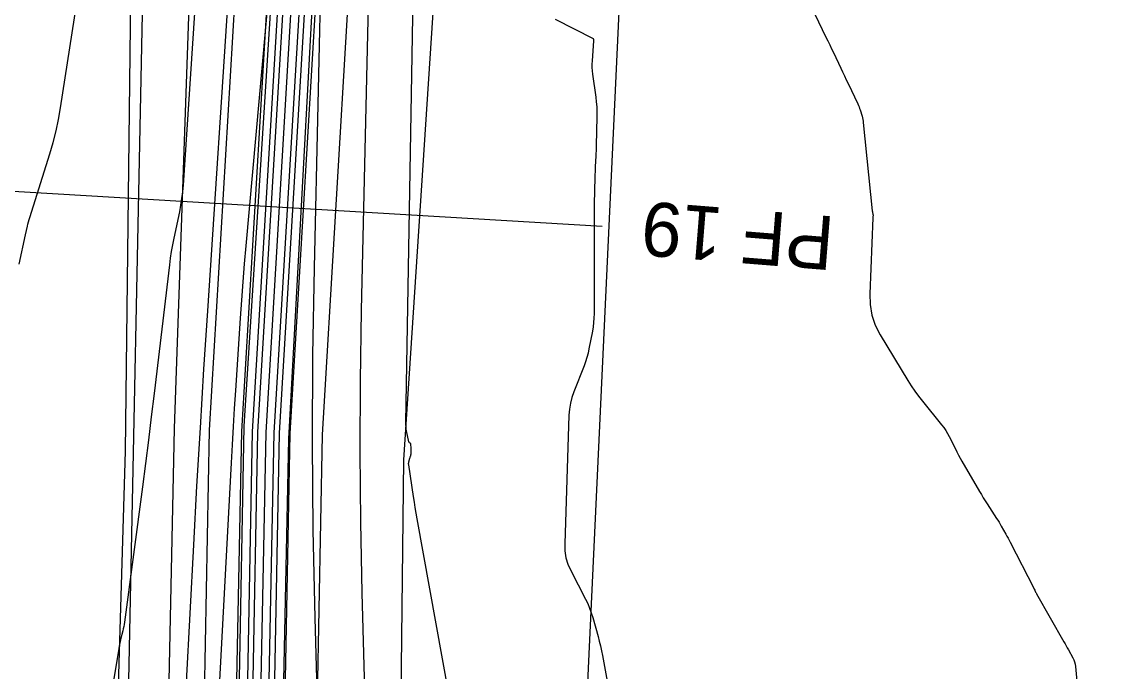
# Model space of a CAD drawing. Extents: x -534410 to -534262, y -1190162 to -1189584.
# Drawn here: x -534369.58 to -534349.13, y -1189689.33 to -1189677.27 of the extents above; entities that cross this region are included whole.
import ezdxf

# ---------------------------------------------------------------- set-up
doc = ezdxf.new("R2010")
doc.units = 0
for name, color, linetype in [('30', 7, 'Continuous'), ('31', 7, 'Continuous'), ('_linie', 7, 'Continuous'), ('_N_osa', 7, 'Continuous'), ('_N_tenká', 7, 'Continuous'), ('_N_tenká_velmi', 7, 'Continuous'), ('_N_text', 7, 'Continuous'), ('_tenka', 7, 'Continuous'), ('Default', 7, 'Continuous'), ('Hranice parcel', 7, 'Continuous')]:
    doc.layers.add(name, color=color, linetype=linetype)

msp = doc.modelspace()

# ---------------------------------------------------------------- linework, layer by layer
at = {"layer": '30'}
for points in [[(-534359.666, -1189700.773), (-534362.25, -1189686.484), (-534362.268, -1189686.382), (-534362.286, -1189686.279), (-534362.302, -1189686.177), (-534362.318, -1189686.074), (-534362.407, -1189685.485), (-534362.409, -1189685.471), (-534362.409, -1189685.457), (-534362.407, -1189685.444), (-534362.404, -1189685.43), (-534362.384, -1189685.358), (-534362.381, -1189685.35), (-534362.378, -1189685.341), (-534362.371, -1189685.323), (-534362.369, -1189685.317), (-534362.368, -1189685.311), (-534362.365, -1189685.295), (-534362.364, -1189685.289), (-534362.364, -1189685.286), (-534362.364, -1189685.219), (-534362.364, -1189685.208), (-534362.363, -1189685.181), (-534362.363, -1189685.17), (-534362.363, -1189685.166), (-534362.366, -1189685.115), (-534362.366, -1189685.108), (-534362.365, -1189685.095), (-534362.365, -1189685.092), (-534362.366, -1189685.09), (-534362.367, -1189685.089), (-534362.369, -1189685.087), (-534362.392, -1189685.076), (-534362.396, -1189685.073), (-534362.399, -1189685.07), (-534362.401, -1189685.066), (-534362.403, -1189685.061), (-534362.445, -1189684.854), (-534362.451, -1189684.817), (-534362.456, -1189684.781), (-534362.458, -1189684.744), (-534362.459, -1189684.707), (-534362.015, -1189658.872)], [(-534365.801, -1189668.276), (-534366.596, -1189680.297), (-534366.607, -1189680.421), (-534366.622, -1189680.545), (-534366.641, -1189680.668), (-534366.664, -1189680.791), (-534366.767, -1189681.279), (-534366.792, -1189681.402), (-534366.813, -1189681.525), (-534366.832, -1189681.648), (-534366.848, -1189681.772), (-534367.133, -1189684.164), (-534367.186, -1189684.597), (-534367.239, -1189685.03), (-534367.295, -1189685.462), (-534367.351, -1189685.894), (-534367.683, -1189688.404), (-534367.689, -1189688.445), (-534367.697, -1189688.486), (-534367.705, -1189688.527), (-534367.715, -1189688.567), (-534367.756, -1189688.728), (-534367.765, -1189688.768), (-534367.774, -1189688.809), (-534367.783, -1189688.85), (-534367.79, -1189688.891), (-534368.719, -1189694.516)], [(-534363.782, -1189701.447), (-534364.144, -1189688.321), (-534364.178, -1189686.697), (-534364.192, -1189685.074), (-534364.185, -1189683.451), (-534364.158, -1189681.827), (-534363.949, -1189672.734)], [(-534364.818, -1189674.62), (-534365.429, -1189681.422), (-534365.458, -1189681.757), (-534365.485, -1189682.092), (-534365.51, -1189682.427), (-534365.533, -1189682.763), (-534365.622, -1189684.105), (-534365.644, -1189684.441), (-534365.664, -1189684.776), (-534365.684, -1189685.112), (-534365.702, -1189685.448), (-534366.553, -1189701.366)], [(-534354.935, -1189676.979), (-534354.661, -1189677.55), (-534354.626, -1189677.622), (-534354.592, -1189677.693), (-534354.558, -1189677.765), (-534354.524, -1189677.837), (-534354.387, -1189678.125), (-534354.353, -1189678.197), (-534354.319, -1189678.269), (-534354.284, -1189678.341), (-534354.25, -1189678.413), (-534354.07, -1189678.79), (-534354.058, -1189678.817), (-534354.046, -1189678.845), (-534354.036, -1189678.874), (-534354.027, -1189678.902), (-534353.992, -1189679.018), (-534353.984, -1189679.047), (-534353.978, -1189679.077), (-534353.973, -1189679.107), (-534353.969, -1189679.136), (-534353.802, -1189680.773), (-534353.801, -1189680.78), (-534353.8, -1189680.787), (-534353.799, -1189680.794), (-534353.797, -1189680.802), (-534353.79, -1189680.833), (-534353.789, -1189680.839), (-534353.788, -1189680.845), (-534353.788, -1189680.85), (-534353.788, -1189680.856), (-534353.789, -1189680.884), (-534353.789, -1189680.901), (-534353.849, -1189682.312), (-534353.844, -1189682.513), (-534353.809, -1189682.706), (-534353.746, -1189682.892), (-534353.655, -1189683.071), (-534353.139, -1189683.921), (-534353.077, -1189684.019), (-534353.012, -1189684.115), (-534352.944, -1189684.209), (-534352.872, -1189684.301), (-534352.514, -1189684.744), (-534352.475, -1189684.795), (-534352.439, -1189684.848), (-534352.406, -1189684.903), (-534352.376, -1189684.959), (-534352.26, -1189685.189), (-534352.231, -1189685.246), (-534352.201, -1189685.303), (-534352.17, -1189685.359), (-534352.138, -1189685.415), (-534351.811, -1189685.978), (-534351.777, -1189686.036), (-534351.742, -1189686.094), (-534351.706, -1189686.151), (-534351.669, -1189686.208), (-534351.494, -1189686.479), (-534351.472, -1189686.514), (-534351.449, -1189686.55), (-534351.428, -1189686.587), (-534351.407, -1189686.623), (-534351.323, -1189686.771), (-534351.302, -1189686.808), (-534351.282, -1189686.845), (-534351.262, -1189686.882), (-534351.243, -1189686.92), (-534350.804, -1189687.775), (-534350.795, -1189687.793), (-534350.786, -1189687.81), (-534350.769, -1189687.845), (-534350.765, -1189687.854), (-534350.761, -1189687.862), (-534350.756, -1189687.871), (-534350.751, -1189687.879), (-534350.245, -1189688.771), (-534350.224, -1189688.808), (-534350.203, -1189688.845), (-534350.182, -1189688.881), (-534350.162, -1189688.918), (-534350.079, -1189689.065), (-534350.06, -1189689.103), (-534350.046, -1189689.141), (-534350.036, -1189689.181), (-534350.03, -1189689.223), (-534349.902, -1189690.649)]]:
    msp.add_lwpolyline(points, dxfattribs=at)
at = {"layer": '31'}
for points in [[(-534366.669, -1189692.065), (-534366.397, -1189686.966), (-534366.337, -1189685.881), (-534366.274, -1189684.796), (-534366.207, -1189683.711), (-534366.137, -1189682.626), (-534365.732, -1189676.49), (-534365.636, -1189675.106), (-534365.532, -1189673.723), (-534365.42, -1189672.34), (-534365.3, -1189670.958), (-534363.781, -1189654.053)], [(-534362.676, -1189654.218), (-534362.693, -1189655.065), (-534362.774, -1189659.756), (-534362.793, -1189660.82), (-534362.813, -1189661.885), (-534362.835, -1189662.949), (-534362.859, -1189664.013), (-534363.288, -1189682.613), (-534363.31, -1189683.924), (-534363.316, -1189685.235), (-534363.304, -1189686.546), (-534363.277, -1189687.857), (-534363.128, -1189693.255)], [(-534369.64, -1189681.764), (-534369.521, -1189681.219), (-534369.485, -1189681.057), (-534369.476, -1189681.017), (-534369.465, -1189680.976), (-534369.454, -1189680.936), (-534369.442, -1189680.897), (-534369.068, -1189679.715), (-534369.006, -1189679.504), (-534368.951, -1189679.291), (-534368.905, -1189679.076), (-534368.867, -1189678.859), (-534367.627, -1189670.868)], [(-534359.686, -1189677.219), (-534358.985, -1189677.578), (-534358.982, -1189677.58), (-534358.98, -1189677.583), (-534358.978, -1189677.586), (-534358.977, -1189677.589), (-534358.976, -1189677.605), (-534358.976, -1189677.612), (-534358.976, -1189677.62), (-534359.002, -1189677.988), (-534359.005, -1189678.05), (-534359.005, -1189678.112), (-534359.001, -1189678.175), (-534358.994, -1189678.237), (-534358.935, -1189678.662), (-534358.924, -1189678.753), (-534358.917, -1189678.845), (-534358.914, -1189678.937), (-534358.914, -1189679.029), (-534358.926, -1189679.561), (-534358.928, -1189679.61), (-534358.929, -1189679.659), (-534358.931, -1189679.708), (-534358.933, -1189679.756), (-534358.943, -1189679.951), (-534358.945, -1189680), (-534358.947, -1189680.049), (-534358.949, -1189680.098), (-534358.95, -1189680.147), (-534358.962, -1189680.646), (-534358.964, -1189680.745), (-534358.966, -1189680.845), (-534358.967, -1189680.944), (-534358.967, -1189681.043), (-534358.967, -1189682.679), (-534358.969, -1189682.761), (-534358.975, -1189682.844), (-534358.985, -1189682.926), (-534358.998, -1189683.008), (-534359.06, -1189683.334), (-534359.077, -1189683.414), (-534359.099, -1189683.494), (-534359.123, -1189683.573), (-534359.152, -1189683.651), (-534359.341, -1189684.129), (-534359.378, -1189684.235), (-534359.405, -1189684.343), (-534359.423, -1189684.453), (-534359.432, -1189684.566), (-534359.511, -1189686.953), (-534359.507, -1189687.082), (-534359.487, -1189687.207), (-534359.451, -1189687.328), (-534359.399, -1189687.446), (-534359.123, -1189687.979), (-534359.083, -1189688.06), (-534359.048, -1189688.144), (-534359.017, -1189688.23), (-534358.99, -1189688.317), (-534358.892, -1189688.669), (-534358.869, -1189688.757), (-534358.847, -1189688.845), (-534358.828, -1189688.935), (-534358.81, -1189689.024), (-534358.684, -1189689.701)]]:
    msp.add_lwpolyline(points, dxfattribs=at)
at = {"layer": '_linie'}
for points in [[(-534366.12, -1189620.81), (-534364.52, -1189627.2), (-534365.69, -1189653.8), (-534366.76, -1189684.81), (-534368.14, -1189748.73), (-534368.38, -1189779.14), (-534368.65, -1189820.64), (-534368.59, -1189847.58), (-534367.2, -1189913.8)], [(-534363.12, -1189621.02), (-534362.79, -1189621.58), (-534361.82, -1189627.79), (-534363.46, -1189653.55), (-534365.47, -1189684.77), (-534366.65, -1189748.83), (-534366.75, -1189779.47), (-534366.9, -1189820.47), (-534366.95, -1189846.72), (-534366.338, -1189888.804), (-534363.85, -1189911.95), (-534357.07, -1189929.19), (-534352.334, -1189940.856)], [(-534359.03, -1189621.26), (-534359.41, -1189621.83), (-534360.84, -1189627.76), (-534362.92, -1189653.56), (-534364.64, -1189685), (-534365.94, -1189748.9), (-534366.02, -1189779.52), (-534366.03, -1189820.5), (-534366.48, -1189846.73), (-534365.511, -1189888.873), (-534362.72, -1189912.12), (-534356.62, -1189928.64), (-534351.589, -1189940.594)]]:
    msp.add_lwpolyline(points, dxfattribs=at)
at = {"layer": '_N_osa'}
msp.add_lwpolyline([(-534351.95, -1189940.722), (-534356.845, -1189928.915), (-534363.285, -1189912.035), (-534365.925, -1189888.838), (-534366.715, -1189846.725), (-534366.465, -1189820.485), (-534366.385, -1189779.495), (-534366.295, -1189748.865), (-534365.055, -1189684.885), (-534363.19, -1189653.555), (-534361.333, -1189627.822)], dxfattribs=at)
at = {"layer": '_N_tenká'}
for points in [[(-534352.92, -1189941.124), (-534357.821, -1189929.303), (-534364.313, -1189912.285), (-534366.973, -1189888.908), (-534367.765, -1189846.73), (-534367.515, -1189820.479), (-534367.435, -1189779.492), (-534367.345, -1189748.853), (-534366.104, -1189684.844), (-534364.238, -1189653.486), (-534362.424, -1189628.352), (-534361.782, -1189627.792)], [(-534350.98, -1189940.319), (-534355.869, -1189928.527), (-534362.257, -1189911.785), (-534364.876, -1189888.769), (-534365.665, -1189846.72), (-534365.415, -1189820.491), (-534365.335, -1189779.498), (-534365.245, -1189748.877), (-534364.006, -1189684.926), (-534362.142, -1189653.624), (-534360.329, -1189628.488), (-534360.884, -1189627.851)]]:
    msp.add_lwpolyline(points, dxfattribs=at)
at = {"layer": '_N_tenká_velmi'}
for points in [[(-534352.366, -1189940.894), (-534357.263, -1189929.081), (-534363.726, -1189912.142), (-534366.374, -1189888.868), (-534367.165, -1189846.727), (-534366.915, -1189820.482), (-534366.835, -1189779.494), (-534366.745, -1189748.86), (-534365.505, -1189684.867), (-534363.639, -1189653.525), (-534361.782, -1189627.792)], [(-534352.181, -1189940.817), (-534357.077, -1189929.007), (-534363.53, -1189912.095), (-534366.174, -1189888.855), (-534366.965, -1189846.726), (-534366.715, -1189820.484), (-534366.635, -1189779.494), (-534366.545, -1189748.862), (-534365.305, -1189684.875), (-534363.439, -1189653.539), (-534361.583, -1189627.805)], [(-534352.089, -1189940.779), (-534356.984, -1189928.97), (-534363.432, -1189912.071), (-534366.074, -1189888.848), (-534366.865, -1189846.726), (-534366.615, -1189820.484), (-534366.535, -1189779.495), (-534366.445, -1189748.863), (-534365.205, -1189684.879), (-534363.34, -1189653.545), (-534361.483, -1189627.812)], [(-534351.812, -1189940.664), (-534356.706, -1189928.86), (-534363.138, -1189911.999), (-534365.775, -1189888.828), (-534366.565, -1189846.724), (-534366.315, -1189820.486), (-534366.235, -1189779.495), (-534366.145, -1189748.867), (-534364.905, -1189684.891), (-534363.04, -1189653.565), (-534361.184, -1189627.831)], [(-534351.719, -1189940.626), (-534356.613, -1189928.823), (-534363.04, -1189911.975), (-534365.675, -1189888.822), (-534366.465, -1189846.724), (-534366.215, -1189820.486), (-534366.135, -1189779.496), (-534366.045, -1189748.868), (-534364.805, -1189684.895), (-534362.941, -1189653.571), (-534361.084, -1189627.838)], [(-534351.534, -1189940.549), (-534356.427, -1189928.749), (-534362.844, -1189911.928), (-534365.475, -1189888.808), (-534366.265, -1189846.723), (-534366.015, -1189820.488), (-534365.935, -1189779.496), (-534365.845, -1189748.87), (-534364.605, -1189684.903), (-534362.741, -1189653.585), (-534360.884, -1189627.851)]]:
    msp.add_lwpolyline(points, dxfattribs=at)
at = {"layer": '_N_text'}
msp.add_lwpolyline([(-534358.817, -1189681.064), (-534370.796, -1189680.351)], dxfattribs=at)
at = {"layer": '_tenka'}
for points in [[(-534349.13, -1189939.73), (-534354.63, -1189926.96), (-534362.03, -1189907.65), (-534364.521, -1189888.74), (-534364.47, -1189846.64), (-534364.29, -1189820.63), (-534364.22, -1189780.69), (-534363.18, -1189749.38), (-534362.5, -1189685.39), (-534360.27, -1189651.6), (-534357.03, -1189627.34), (-534354.77, -1189620.37)], [(-534366.12, -1189620.81), (-534364.52, -1189627.2), (-534365.69, -1189653.8), (-534366.76, -1189684.81), (-534368.14, -1189748.73), (-534368.38, -1189779.14), (-534368.65, -1189820.64), (-534368.59, -1189847.58), (-534367.2, -1189913.8)], [(-534366.12, -1189620.81), (-534364.52, -1189627.2), (-534365.69, -1189653.8), (-534366.76, -1189684.81), (-534368.14, -1189748.73), (-534368.38, -1189779.14), (-534368.65, -1189820.64), (-534368.59, -1189847.58), (-534367.2, -1189913.8)], [(-534363.12, -1189621.02), (-534362.79, -1189621.58), (-534361.82, -1189627.79), (-534363.46, -1189653.55), (-534365.47, -1189684.77), (-534366.65, -1189748.83), (-534366.75, -1189779.47), (-534366.9, -1189820.47), (-534366.95, -1189846.72), (-534366.338, -1189888.804), (-534363.85, -1189911.95), (-534357.07, -1189929.19), (-534352.334, -1189940.856)], [(-534363.12, -1189621.02), (-534362.79, -1189621.58), (-534361.82, -1189627.79), (-534363.46, -1189653.55), (-534365.47, -1189684.77), (-534366.65, -1189748.83), (-534366.75, -1189779.47), (-534366.9, -1189820.47), (-534366.95, -1189846.72), (-534366.338, -1189888.804), (-534363.85, -1189911.95), (-534357.07, -1189929.19), (-534352.334, -1189940.856)], [(-534359.03, -1189621.26), (-534359.41, -1189621.83), (-534360.84, -1189627.76), (-534362.92, -1189653.56), (-534364.64, -1189685), (-534365.94, -1189748.9), (-534366.02, -1189779.52), (-534366.03, -1189820.5), (-534366.48, -1189846.73), (-534365.511, -1189888.873), (-534362.72, -1189912.12), (-534356.62, -1189928.64), (-534351.589, -1189940.594)], [(-534359.03, -1189621.26), (-534359.41, -1189621.83), (-534360.84, -1189627.76), (-534362.92, -1189653.56), (-534364.64, -1189685), (-534365.94, -1189748.9), (-534366.02, -1189779.52), (-534366.03, -1189820.5), (-534366.48, -1189846.73), (-534365.511, -1189888.873), (-534362.72, -1189912.12), (-534356.62, -1189928.64), (-534351.589, -1189940.594)], [(-534368.65, -1189626.81), (-534368.65, -1189626.81), (-534367.31, -1189654.04), (-534367.67, -1189685.23), (-534369.56, -1189748.93), (-534369.48, -1189778.6), (-534369.45, -1189820.62), (-534369.45, -1189847.87), (-534371.206, -1189896.071), (-534372.39, -1189914.47)]]:
    msp.add_lwpolyline(points, dxfattribs=at)
at = {"layer": 'Default'}
for p, q in [((-534367.31, -1189654.04), (-534367.67, -1189685.23)), ((-534367.67, -1189685.23), (-534369.56, -1189748.93))]:
    msp.add_line(p, q, dxfattribs=at)
msp.add_lwpolyline([(-534349.13, -1189939.73), (-534354.63, -1189926.96), (-534362.03, -1189907.65), (-534364.521, -1189888.74), (-534364.47, -1189846.64), (-534364.29, -1189820.63), (-534364.22, -1189780.69), (-534363.18, -1189749.38), (-534362.5, -1189685.39), (-534360.27, -1189651.6), (-534357.03, -1189627.34), (-534354.77, -1189620.37)], dxfattribs=at)
at = {"layer": 'Hranice parcel'}
for p, q in [((-534359.48, -1189697.97), (-534356.61, -1189636.93)), ((-534366.56, -1189638.19), (-534367.77, -1189697.34))]:
    msp.add_line(p, q, dxfattribs=at)

# ---------------------------------------------------------------- texts
at = {"layer": '_N_text'}
msp.add_text('PF 19', height=1, rotation=175.4144, dxfattribs=at).set_placement((-534354.479, -1189680.881))

doc.saveas('drawing.dxf')
